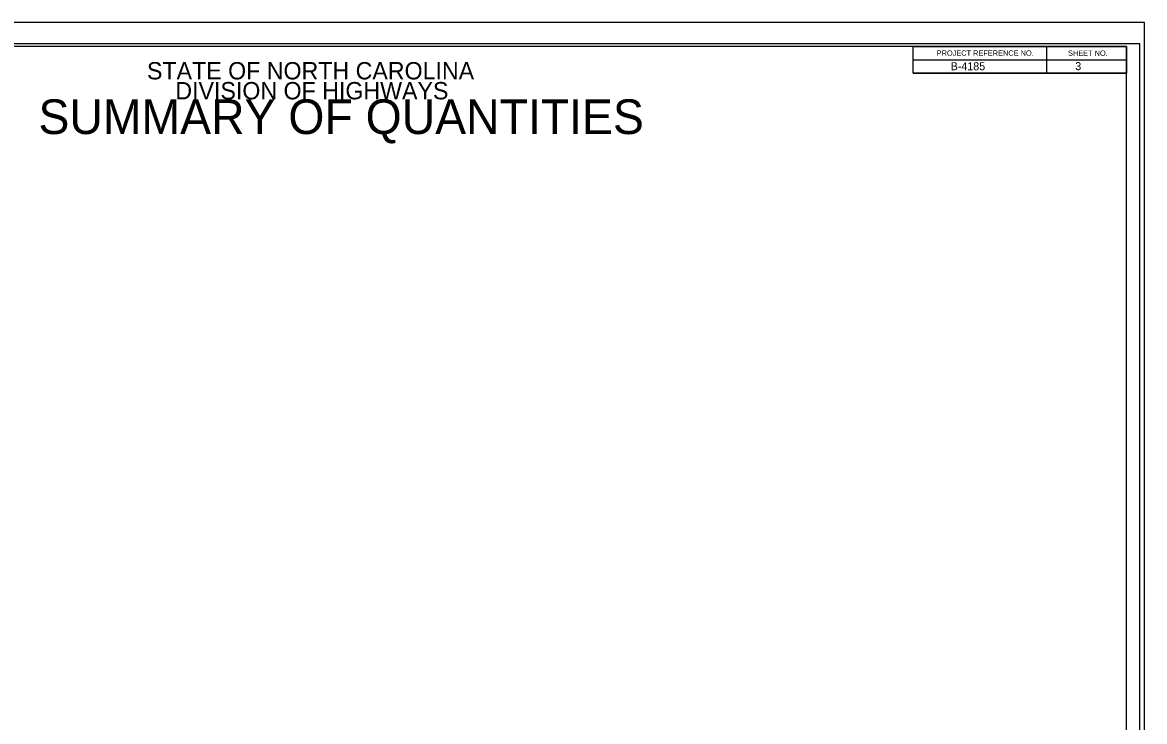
# Model space of a CAD drawing. Extents: x 2530399 to 2530799, y 189629 to 189994.
# Drawn here: x 2530464.8 to 2530569.9, y 189928 to 189993.5 of the extents above; entities that cross this region are included whole.
import ezdxf

# ---------------------------------------------------------------- set-up
doc = ezdxf.new("R2010")
doc.units = 0
for name, color, linetype in [('Old_Level_24', 7, 'Continuous'), ('Sheet Cutting Line CELL', 7, 'Continuous'), ('Sheet Data Field CELL', 7, 'Continuous'), ('Sheet Plan CELL', 7, 'Continuous'), ('Sheet Plot Border Inside CELL', 7, 'Continuous'), ('Sheet Plot Border Outside CELL', 7, 'Continuous')]:
    doc.layers.add(name, color=color, linetype=linetype)

msp = doc.modelspace()

# ---------------------------------------------------------------- linework, layer by layer
at = {"layer": 'Sheet Cutting Line CELL'}
for p, q in [((2530569.94, 189993.51), (2530401.59, 189993.51)), ((2530544.32, 189991.26), (2530423.24, 189991.26))]:
    msp.add_line(p, q, dxfattribs=at)
at = {"layer": 'Sheet Plan CELL'}
for p, q in [((2530560.74, 189991.26), (2530560.74, 189988.76)), ((2530548.24, 189990.01), (2530568.24, 189990.01)), ((2530548.24, 189988.76), (2530568.24, 189988.76)), ((2530548.24, 189988.76), (2530568.24, 189988.76))]:
    msp.add_line(p, q, dxfattribs=at)
for points in [[(2530568.24, 189991.26), (2530418.24, 189991.26), (2530418.24, 189886.26), (2530568.24, 189886.26)], [(2530548.24, 189991.26), (2530568.24, 189991.26), (2530568.24, 189988.76), (2530548.24, 189988.76)]]:
    msp.add_lwpolyline(points, close=True, dxfattribs=at)
at = {"layer": 'Sheet Plot Border Inside CELL'}
msp.add_lwpolyline([(2530402.89, 189886.01), (2530569.49, 189886.01), (2530569.49, 189991.51), (2530402.89, 189991.51)], close=True, dxfattribs=at)
at = {"layer": 'Sheet Plot Border Outside CELL'}
msp.add_lwpolyline([(2530401.59, 189884.01), (2530569.94, 189884.01), (2530569.94, 189993.51), (2530401.59, 189993.51)], close=True, dxfattribs=at)

# ---------------------------------------------------------------- texts
at = {"layer": 'Old_Level_24'}
for s, height, p in [('STATE OF NORTH CAROLINA', 1.625, (2530476.44, 189988.17)), ('DIVISION OF HIGHWAYS', 1.625, (2530479.1, 189986.3)), ('SUMMARY OF QUANTITIES', 3.25, (2530466.27, 189983.05))]:
    msp.add_text(s, height=height, dxfattribs=at).set_placement(p)
at = {"layer": 'Sheet Data Field CELL'}
for s, p in [('B-4185   ', (2530551.77, 189989.03)), ('3  ', (2530563.45, 189989.04))]:
    msp.add_text(s, height=0.75, rotation=0, dxfattribs=at).set_placement(p)
at = {"layer": 'Sheet Plan CELL'}
for s, p in [('PROJECT REFERENCE NO.', (2530550.46, 189990.39)), ('SHEET NO.', (2530562.77, 189990.38))]:
    msp.add_text(s, height=0.5, rotation=0, dxfattribs=at).set_placement(p)

doc.saveas('drawing.dxf')
